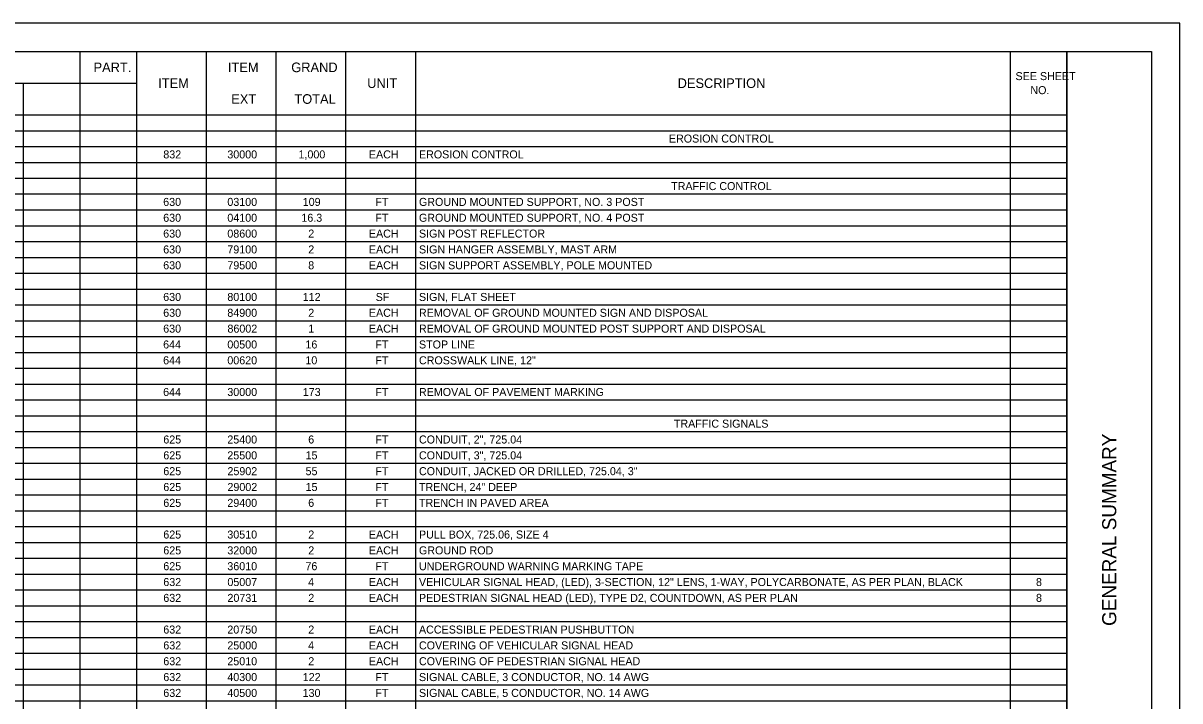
# Model space of a CAD drawing. Extents: x 0 to 34, y 0 to 22.
# Drawn here: x 13.53 to 34, y 10.02 to 22 of the extents above; entities that cross this region are included whole.
import ezdxf

# ---------------------------------------------------------------- set-up
doc = ezdxf.new("R2010")
doc.units = 0
for name, color, linetype in [('Default', 7, 'Continuous'), ('SH_Border', 7, 'Continuous'), ('SH_Cut_Line', 7, 'Continuous'), ('SH_Data', 7, 'Continuous')]:
    doc.layers.add(name, color=color, linetype=linetype)

msp = doc.modelspace()

# ---------------------------------------------------------------- linework, layer by layer
at = {"layer": 'Default'}
for p, q in [((12.528, 21.499), (13.53, 21.499)), ((13.53, 21.499), (15.535, 21.499)), ((14.533, 21.499), (14.533, 21.219)), ((15.535, 21.499), (32, 21.499)), ((15.535, 21.499), (15.535, 21.219)), ((16.769, 21.499), (16.769, 21.219)), ((18.003, 21.499), (18.003, 21.219)), ((19.237, 21.499), (19.237, 21.219)), ((20.471, 21.499), (20.471, 21.219)), ((30.997, 21.499), (30.997, 21.219)), ((32, 21.499), (32, 21.219)), ((14.533, 21.219), (14.533, 20.939)), ((15.535, 21.219), (15.535, 20.939)), ((16.769, 21.219), (16.769, 20.939)), ((18.003, 21.219), (18.003, 20.939)), ((19.237, 21.219), (19.237, 20.939)), ((20.471, 21.219), (20.471, 20.939)), ((30.997, 21.219), (30.997, 20.939)), ((32, 21.219), (32, 20.939)), ((12.528, 20.939), (13.53, 20.939)), ((13.53, 20.939), (15.535, 20.939)), ((13.53, 20.939), (13.53, 20.659)), ((14.533, 20.939), (14.533, 20.659)), ((15.535, 20.939), (15.535, 20.659)), ((16.769, 20.939), (16.769, 20.659)), ((18.003, 20.939), (18.003, 20.659)), ((19.237, 20.939), (19.237, 20.659)), ((20.471, 20.939), (20.471, 20.659)), ((30.997, 20.939), (30.997, 20.659)), ((32, 20.939), (32, 20.659)), ((13.53, 20.659), (13.53, 20.379)), ((14.533, 20.659), (14.533, 20.379)), ((15.535, 20.659), (15.535, 20.379)), ((16.769, 20.659), (16.769, 20.379)), ((18.003, 20.659), (18.003, 20.379)), ((19.237, 20.659), (19.237, 20.379)), ((20.471, 20.659), (20.471, 20.379)), ((30.997, 20.659), (30.997, 20.379)), ((32, 20.659), (32, 20.379)), ((12.528, 20.379), (13.53, 20.379)), ((13.53, 20.379), (15.535, 20.379)), ((13.53, 20.379), (13.53, 20.099)), ((14.533, 20.379), (14.533, 20.099)), ((15.535, 20.379), (32, 20.379)), ((15.535, 20.379), (15.535, 20.099)), ((16.769, 20.379), (16.769, 20.099)), ((18.003, 20.379), (18.003, 20.099)), ((19.237, 20.379), (19.237, 20.099)), ((20.471, 20.379), (20.471, 20.099)), ((30.997, 20.379), (30.997, 20.099)), ((32, 20.379), (32, 20.099)), ((12.528, 20.099), (13.53, 20.099)), ((13.53, 20.099), (15.535, 20.099)), ((13.53, 20.099), (13.53, 18.7)), ((14.533, 20.099), (14.533, 18.7)), ((15.535, 20.099), (32, 20.099)), ((15.535, 20.099), (15.535, 18.7)), ((16.769, 20.099), (16.769, 18.7)), ((18.003, 20.099), (18.003, 18.7)), ((19.237, 20.099), (19.237, 18.7)), ((20.471, 20.099), (20.471, 18.7)), ((30.997, 20.099), (30.997, 18.7)), ((32, 20.099), (32, 18.7)), ((12.528, 19.819), (13.53, 19.819)), ((13.53, 19.819), (15.535, 19.819)), ((15.535, 19.819), (32, 19.819)), ((12.528, 19.539), (13.53, 19.539)), ((13.53, 19.539), (15.535, 19.539)), ((15.535, 19.539), (32, 19.539)), ((12.528, 19.259), (13.53, 19.259)), ((13.53, 19.259), (15.535, 19.259)), ((15.535, 19.259), (32, 19.259)), ((12.528, 18.98), (13.53, 18.98)), ((13.53, 18.98), (15.535, 18.98)), ((15.535, 18.98), (32, 18.98)), ((12.528, 18.7), (13.53, 18.7)), ((13.53, 18.7), (15.535, 18.7)), ((13.53, 18.7), (13.53, 18.14)), ((14.533, 18.7), (14.533, 18.14)), ((15.535, 18.7), (32, 18.7)), ((15.535, 18.7), (15.535, 18.14)), ((16.769, 18.7), (16.769, 18.14)), ((18.003, 18.7), (18.003, 18.14)), ((19.237, 18.7), (19.237, 18.14)), ((20.471, 18.7), (20.471, 18.14)), ((30.997, 18.7), (30.997, 18.14)), ((32, 18.7), (32, 18.14)), ((12.528, 18.42), (13.53, 18.42)), ((13.53, 18.42), (15.535, 18.42)), ((15.535, 18.42), (32, 18.42)), ((12.528, 18.14), (13.53, 18.14)), ((13.53, 18.14), (15.535, 18.14)), ((13.53, 18.14), (13.53, 17.86)), ((14.533, 18.14), (14.533, 17.86)), ((15.535, 18.14), (32, 18.14)), ((15.535, 18.14), (15.535, 17.86)), ((16.769, 18.14), (16.769, 17.86)), ((18.003, 18.14), (18.003, 17.86)), ((19.237, 18.14), (19.237, 17.86)), ((20.471, 18.14), (20.471, 17.86)), ((30.997, 18.14), (30.997, 17.86)), ((32, 18.14), (32, 17.86)), ((12.528, 17.86), (13.53, 17.86)), ((13.53, 17.86), (15.535, 17.86)), ((13.53, 17.86), (13.53, 17.58)), ((14.533, 17.86), (14.533, 17.58)), ((15.535, 17.86), (32, 17.86)), ((15.535, 17.86), (15.535, 17.58)), ((16.769, 17.86), (16.769, 17.58)), ((18.003, 17.86), (18.003, 17.58)), ((19.237, 17.86), (19.237, 17.58)), ((20.471, 17.86), (20.471, 17.58)), ((30.997, 17.86), (30.997, 17.58)), ((32, 17.86), (32, 17.58)), ((12.528, 17.58), (13.53, 17.58)), ((13.53, 17.58), (15.535, 17.58)), ((13.53, 17.58), (13.53, 17.3)), ((14.533, 17.58), (14.533, 17.3)), ((15.535, 17.58), (32, 17.58)), ((15.535, 17.58), (15.535, 17.3)), ((16.769, 17.58), (16.769, 17.3)), ((18.003, 17.58), (18.003, 17.3)), ((19.237, 17.58), (19.237, 17.3)), ((20.471, 17.58), (20.471, 17.3)), ((30.997, 17.58), (30.997, 17.3)), ((32, 17.58), (32, 17.3)), ((12.528, 17.3), (13.53, 17.3)), ((13.53, 17.3), (15.535, 17.3)), ((13.53, 17.3), (13.53, 17.02)), ((14.533, 17.3), (14.533, 17.02)), ((15.535, 17.3), (32, 17.3)), ((15.535, 17.3), (15.535, 17.02)), ((16.769, 17.3), (16.769, 17.02)), ((18.003, 17.3), (18.003, 17.02)), ((19.237, 17.3), (19.237, 17.02)), ((20.471, 17.3), (20.471, 17.02)), ((30.997, 17.3), (30.997, 17.02)), ((32, 17.3), (32, 17.02)), ((12.528, 17.02), (13.53, 17.02)), ((13.53, 17.02), (15.535, 17.02)), ((13.53, 17.02), (13.53, 16.74)), ((14.533, 17.02), (14.533, 16.74)), ((15.535, 17.02), (32, 17.02)), ((15.535, 17.02), (15.535, 16.74)), ((16.769, 17.02), (16.769, 16.74)), ((18.003, 17.02), (18.003, 16.74)), ((19.237, 17.02), (19.237, 16.74)), ((20.471, 17.02), (20.471, 16.74)), ((30.997, 17.02), (30.997, 16.74)), ((32, 17.02), (32, 16.74)), ((12.528, 16.74), (13.53, 16.74)), ((13.53, 16.74), (15.535, 16.74)), ((13.53, 16.74), (13.53, 16.18)), ((14.533, 16.74), (14.533, 16.18)), ((15.535, 16.74), (32, 16.74)), ((15.535, 16.74), (15.535, 16.18)), ((16.769, 16.74), (16.769, 16.18)), ((18.003, 16.74), (18.003, 16.18)), ((19.237, 16.74), (19.237, 16.18)), ((20.471, 16.74), (20.471, 16.18)), ((30.997, 16.74), (30.997, 16.18)), ((32, 16.74), (32, 16.18)), ((12.528, 16.46), (13.53, 16.46)), ((13.53, 16.46), (15.535, 16.46)), ((15.535, 16.46), (32, 16.46)), ((12.528, 16.18), (13.53, 16.18)), ((13.53, 16.18), (15.535, 16.18)), ((13.53, 16.18), (13.53, 15.9)), ((14.533, 16.18), (14.533, 15.9)), ((15.535, 16.18), (32, 16.18)), ((15.535, 16.18), (15.535, 15.9)), ((16.769, 16.18), (16.769, 15.9)), ((18.003, 16.18), (18.003, 15.9)), ((19.237, 16.18), (19.237, 15.9)), ((20.471, 16.18), (20.471, 15.9)), ((30.997, 16.18), (30.997, 15.9)), ((32, 16.18), (32, 15.9)), ((12.528, 15.9), (13.53, 15.9)), ((13.53, 15.9), (15.535, 15.9)), ((13.53, 15.9), (13.53, 15.62)), ((14.533, 15.9), (14.533, 15.62)), ((15.535, 15.9), (32, 15.9)), ((15.535, 15.9), (15.535, 15.62)), ((16.769, 15.9), (16.769, 15.62)), ((18.003, 15.9), (18.003, 15.62)), ((19.237, 15.9), (19.237, 15.62)), ((20.471, 15.9), (20.471, 15.62)), ((30.997, 15.9), (30.997, 15.62)), ((32, 15.9), (32, 15.62)), ((12.528, 15.62), (13.53, 15.62)), ((13.53, 15.62), (15.535, 15.62)), ((13.53, 15.62), (13.53, 15.34)), ((14.533, 15.62), (14.533, 15.34)), ((15.535, 15.62), (32, 15.62)), ((15.535, 15.62), (15.535, 15.34)), ((16.769, 15.62), (16.769, 15.34)), ((18.003, 15.62), (18.003, 15.34)), ((19.237, 15.62), (19.237, 15.34)), ((20.471, 15.62), (20.471, 15.34)), ((30.997, 15.62), (30.997, 15.34)), ((32, 15.62), (32, 15.34)), ((12.528, 15.34), (13.53, 15.34)), ((13.53, 15.34), (15.535, 15.34)), ((13.53, 15.34), (13.53, 14.78)), ((14.533, 15.34), (14.533, 14.78)), ((15.535, 15.34), (32, 15.34)), ((15.535, 15.34), (15.535, 14.78)), ((16.769, 15.34), (16.769, 14.78)), ((18.003, 15.34), (18.003, 14.78)), ((19.237, 15.34), (19.237, 14.78)), ((20.471, 15.34), (20.471, 14.78)), ((30.997, 15.34), (30.997, 14.78)), ((32, 15.34), (32, 14.78)), ((12.528, 15.06), (13.53, 15.06)), ((13.53, 15.06), (15.535, 15.06)), ((15.535, 15.06), (32, 15.06)), ((12.528, 14.78), (13.53, 14.78)), ((13.53, 14.78), (15.535, 14.78)), ((13.53, 14.78), (13.53, 14.5)), ((14.533, 14.78), (14.533, 14.5)), ((15.535, 14.78), (32, 14.78)), ((15.535, 14.78), (15.535, 14.5)), ((16.769, 14.78), (16.769, 14.5)), ((18.003, 14.78), (18.003, 14.5)), ((19.237, 14.78), (19.237, 14.5)), ((20.471, 14.78), (20.471, 14.5)), ((30.997, 14.78), (30.997, 14.5)), ((32, 14.78), (32, 14.5)), ((12.528, 14.5), (13.53, 14.5)), ((13.53, 14.5), (15.535, 14.5)), ((13.53, 14.5), (13.53, 14.22)), ((14.533, 14.5), (14.533, 14.22)), ((15.535, 14.5), (32, 14.5)), ((15.535, 14.5), (15.535, 14.22)), ((16.769, 14.5), (16.769, 14.22)), ((18.003, 14.5), (18.003, 14.22)), ((19.237, 14.5), (19.237, 14.22)), ((20.471, 14.5), (20.471, 14.22)), ((30.997, 14.5), (30.997, 14.22)), ((32, 14.5), (32, 14.22)), ((12.528, 14.22), (13.53, 14.22)), ((13.53, 14.22), (15.535, 14.22)), ((13.53, 14.22), (13.53, 13.94)), ((14.533, 14.22), (14.533, 13.94)), ((15.535, 14.22), (32, 14.22)), ((15.535, 14.22), (15.535, 13.94)), ((16.769, 14.22), (16.769, 13.94)), ((18.003, 14.22), (18.003, 13.94)), ((19.237, 14.22), (19.237, 13.94)), ((20.471, 14.22), (20.471, 13.94)), ((30.997, 14.22), (30.997, 13.94)), ((32, 14.22), (32, 13.94)), ((12.528, 13.94), (13.53, 13.94)), ((13.53, 13.94), (15.535, 13.94)), ((13.53, 13.94), (13.53, 11.7)), ((14.533, 13.94), (14.533, 11.7)), ((15.535, 13.94), (32, 13.94)), ((15.535, 13.94), (15.535, 11.7)), ((16.769, 13.94), (16.769, 11.7)), ((18.003, 13.94), (18.003, 11.7)), ((19.237, 13.94), (19.237, 11.7)), ((20.471, 13.94), (20.471, 11.7)), ((30.997, 13.94), (30.997, 11.7)), ((32, 13.94), (32, 11.7)), ((12.528, 13.66), (13.53, 13.66)), ((13.53, 13.66), (15.535, 13.66)), ((15.535, 13.66), (32, 13.66)), ((12.528, 13.38), (13.53, 13.38)), ((13.53, 13.38), (15.535, 13.38)), ((15.535, 13.38), (32, 13.38)), ((12.528, 13.1), (13.53, 13.1)), ((13.53, 13.1), (15.535, 13.1)), ((15.535, 13.1), (32, 13.1)), ((12.528, 12.82), (13.53, 12.82)), ((13.53, 12.82), (15.535, 12.82)), ((15.535, 12.82), (32, 12.82)), ((12.528, 12.54), (13.53, 12.54)), ((13.53, 12.54), (15.535, 12.54)), ((15.535, 12.54), (32, 12.54)), ((12.528, 12.26), (13.53, 12.26)), ((13.53, 12.26), (15.535, 12.26)), ((15.535, 12.26), (32, 12.26)), ((12.528, 11.98), (13.53, 11.98)), ((13.53, 11.98), (15.535, 11.98)), ((15.535, 11.98), (32, 11.98)), ((12.528, 11.7), (13.53, 11.7)), ((13.53, 11.7), (15.535, 11.7)), ((13.53, 11.7), (13.53, 11.42)), ((14.533, 11.7), (14.533, 11.42)), ((15.535, 11.7), (32, 11.7)), ((15.535, 11.7), (15.535, 11.42)), ((16.769, 11.7), (16.769, 11.42)), ((18.003, 11.7), (18.003, 11.42)), ((19.237, 11.7), (19.237, 11.42)), ((20.471, 11.7), (20.471, 11.42)), ((30.997, 11.7), (30.997, 11.42)), ((32, 11.7), (32, 11.42)), ((12.528, 11.42), (13.53, 11.42)), ((13.53, 11.42), (15.535, 11.42)), ((13.53, 11.42), (13.53, 10.3)), ((14.533, 11.42), (14.533, 10.3)), ((15.535, 11.42), (32, 11.42)), ((15.535, 11.42), (15.535, 10.3)), ((16.769, 11.42), (16.769, 10.3)), ((18.003, 11.42), (18.003, 10.3)), ((19.237, 11.42), (19.237, 10.3)), ((20.471, 11.42), (20.471, 10.3)), ((30.997, 11.42), (30.997, 10.3)), ((32, 11.42), (32, 10.3)), ((12.528, 11.14), (13.53, 11.14)), ((13.53, 11.14), (15.535, 11.14)), ((15.535, 11.14), (32, 11.14)), ((12.528, 10.86), (13.53, 10.86)), ((13.53, 10.86), (15.535, 10.86)), ((15.535, 10.86), (32, 10.86)), ((12.528, 10.58), (13.53, 10.58)), ((13.53, 10.58), (15.535, 10.58)), ((15.535, 10.58), (32, 10.58)), ((12.528, 10.3), (13.53, 10.3)), ((13.53, 10.3), (15.535, 10.3)), ((13.53, 10.3), (13.53, 10.02)), ((14.533, 10.3), (14.533, 10.02)), ((15.535, 10.3), (32, 10.3)), ((15.535, 10.3), (15.535, 10.02)), ((16.769, 10.3), (16.769, 10.02)), ((18.003, 10.3), (18.003, 10.02)), ((19.237, 10.3), (19.237, 10.02)), ((20.471, 10.3), (20.471, 10.02)), ((30.997, 10.3), (30.997, 10.02)), ((32, 10.3), (32, 10.02)), ((12.528, 10.02), (13.53, 10.02)), ((13.53, 10.02), (15.535, 10.02)), ((13.53, 10.02), (13.53, 9.74)), ((14.533, 10.02), (14.533, 9.74)), ((15.535, 10.02), (32, 10.02)), ((15.535, 10.02), (15.535, 9.74)), ((16.769, 10.02), (16.769, 9.74)), ((18.003, 10.02), (18.003, 9.74)), ((19.237, 10.02), (19.237, 9.74)), ((20.471, 10.02), (20.471, 9.74)), ((30.997, 10.02), (30.997, 9.74)), ((32, 10.02), (32, 9.74))]:
    msp.add_line(p, q, dxfattribs=at)
at = {"layer": 'SH_Border'}
msp.add_line((32, 0.5), (32, 21.5), dxfattribs=at)
msp.add_lwpolyline([(1.5, 21.5), (33.5, 21.5), (33.5, 0.5), (1.5, 0.5)], close=True, dxfattribs=at)
at = {"layer": 'SH_Cut_Line'}
msp.add_lwpolyline([(0, 0), (34, 0), (34, 22), (0, 22)], close=True, dxfattribs=at)

# ---------------------------------------------------------------- texts
at = {"layer": 'Default'}
for s, height, p in [('PART.', 0.17, (14.776, 21.134)), ('ITEM', 0.17, (17.154, 21.134)), ('GRAND', 0.17, (18.275, 21.134)), ('SEE SHEET ', 0.1417, (31.092, 20.993)), ('ITEM', 0.17, (15.92, 20.854)), ('UNIT', 0.17, (19.619, 20.854)), ('DESCRIPTION', 0.17, (25.112, 20.854)), ('NO.', 0.1417, (31.355, 20.745)), ('EXT', 0.17, (17.213, 20.574)), ('TOTAL', 0.17, (18.33, 20.574)), ('EROSION CONTROL', 0.14166, (24.958, 19.889)), ('832', 0.1417, (16.011, 19.609)), ('30000', 0.1417, (17.144, 19.609)), ('1,000', 0.1417, (18.403, 19.609)), ('EACH', 0.1417, (19.649, 19.609)), ('EROSION CONTROL', 0.14166, (20.535, 19.609)), ('TRAFFIC CONTROL', 0.14166, (24.998, 19.049)), ('630', 0.1417, (16.009, 18.769)), ('03100', 0.1417, (17.144, 18.769)), ('109', 0.1417, (18.478, 18.769)), ('FT', 0.1417, (19.763, 18.769)), ('GROUND MOUNTED SUPPORT, NO. 3 POST', 0.14166, (20.535, 18.769)), ('630', 0.1417, (16.009, 18.489)), ('04100', 0.1417, (17.144, 18.489)), ('16.3', 0.1417, (18.454, 18.489)), ('FT', 0.1417, (19.763, 18.489)), ('GROUND MOUNTED SUPPORT, NO. 4 POST', 0.14166, (20.535, 18.489)), ('630', 0.1417, (16.009, 18.209)), ('08600', 0.1417, (17.144, 18.209)), ('2', 0.142, (18.576, 18.209)), ('EACH', 0.1417, (19.649, 18.209)), ('SIGN POST REFLECTOR', 0.14166, (20.535, 18.209)), ('630', 0.1417, (16.009, 17.929)), ('79100', 0.1417, (17.144, 17.929)), ('2', 0.142, (18.576, 17.929)), ('EACH', 0.1417, (19.649, 17.929)), ('SIGN HANGER ASSEMBLY, MAST ARM', 0.14166, (20.535, 17.929)), ('630', 0.1417, (16.009, 17.649)), ('79500', 0.1417, (17.144, 17.649)), ('8', 0.142, (18.575, 17.649)), ('EACH', 0.1417, (19.649, 17.649)), ('SIGN SUPPORT ASSEMBLY, POLE MOUNTED', 0.14166, (20.535, 17.649)), ('630', 0.1417, (16.009, 17.089)), ('80100', 0.1417, (17.144, 17.089)), ('112', 0.1417, (18.478, 17.089)), ('SF', 0.1417, (19.769, 17.089)), ('SIGN, FLAT SHEET', 0.14166, (20.535, 17.089)), ('630', 0.1417, (16.009, 16.809)), ('84900', 0.1417, (17.144, 16.809)), ('2', 0.142, (18.576, 16.809)), ('EACH', 0.1417, (19.649, 16.809)), ('REMOVAL OF GROUND MOUNTED SIGN AND DISPOSAL', 0.14166, (20.535, 16.809)), ('630', 0.1417, (16.009, 16.529)), ('86002', 0.1417, (17.146, 16.529)), ('1', 0.142, (18.576, 16.529)), ('EACH', 0.1417, (19.649, 16.529)), ('REMOVAL OF GROUND MOUNTED POST SUPPORT AND DISPOSAL', 0.14166, (20.535, 16.529)), ('644', 0.1417, (16.008, 16.249)), ('00500', 0.1417, (17.144, 16.249)), ('16', 0.1417, (18.526, 16.249)), ('FT', 0.1417, (19.763, 16.249)), ('STOP LINE', 0.1417, (20.535, 16.249)), ('644', 0.1417, (16.008, 15.969)), ('00620', 0.1417, (17.144, 15.969)), ('10', 0.1417, (18.525, 15.969)), ('FT', 0.1417, (19.763, 15.969)), ('CROSSWALK LINE, 12"', 0.14166, (20.535, 15.969)), ('644', 0.1417, (16.008, 15.409)), ('30000', 0.1417, (17.144, 15.409)), ('173', 0.1417, (18.479, 15.409)), ('FT', 0.1417, (19.763, 15.409)), ('REMOVAL OF PAVEMENT MARKING', 0.14166, (20.535, 15.409)), ('TRAFFIC SIGNALS', 0.14166, (25.046, 14.849)), ('625', 0.1417, (16.011, 14.569)), ('25400', 0.1417, (17.144, 14.569)), ('6', 0.142, (18.575, 14.569)), ('FT', 0.1417, (19.763, 14.569)), ('CONDUIT, 2", 725.04', 0.14166, (20.535, 14.569)), ('625', 0.1417, (16.011, 14.289)), ('25500', 0.1417, (17.144, 14.289)), ('15', 0.1417, (18.528, 14.289)), ('FT', 0.1417, (19.763, 14.289)), ('CONDUIT, 3", 725.04', 0.14166, (20.535, 14.289)), ('625', 0.1417, (16.011, 14.009)), ('25902', 0.1417, (17.146, 14.009)), ('55', 0.1417, (18.528, 14.009)), ('FT', 0.1417, (19.763, 14.009)), ('CONDUIT, JACKED OR DRILLED, 725.04, 3"', 0.14166, (20.535, 14.009)), ('625', 0.1417, (16.011, 13.729)), ('29002', 0.1417, (17.146, 13.729)), ('15', 0.1417, (18.528, 13.729)), ('FT', 0.1417, (19.763, 13.729)), ('TRENCH, 24" DEEP', 0.14166, (20.535, 13.729)), ('625', 0.1417, (16.011, 13.449)), ('29400', 0.1417, (17.144, 13.449)), ('6', 0.142, (18.575, 13.449)), ('FT', 0.1417, (19.763, 13.449)), ('TRENCH IN PAVED AREA', 0.14166, (20.535, 13.449)), ('625', 0.1417, (16.011, 12.889)), ('30510', 0.1417, (17.144, 12.889)), ('2', 0.142, (18.576, 12.889)), ('EACH', 0.1417, (19.649, 12.889)), ('PULL BOX, 725.06, SIZE 4', 0.14166, (20.535, 12.889)), ('625', 0.1417, (16.011, 12.609)), ('32000', 0.1417, (17.144, 12.609)), ('2', 0.142, (18.576, 12.609)), ('EACH', 0.1417, (19.649, 12.609)), ('GROUND ROD', 0.1417, (20.535, 12.609)), ('625', 0.1417, (16.011, 12.329)), ('36010', 0.1417, (17.144, 12.329)), ('76', 0.1417, (18.526, 12.329)), ('FT', 0.1417, (19.763, 12.329)), ('UNDERGROUND WARNING MARKING TAPE', 0.14166, (20.535, 12.329)), ('632', 0.1417, (16.011, 12.049)), ('05007', 0.1417, (17.145, 12.049)), ('4', 0.142, (18.574, 12.049)), ('EACH', 0.1417, (19.649, 12.049)), ('VEHICULAR SIGNAL HEAD, (LED), 3-SECTION, 12" LENS, 1-WAY, POLYCARBONATE, AS PER PLAN, BLACK', 0.14166, (20.535, 12.049)), ('8', 0.142, (31.454, 12.049)), ('632', 0.1417, (16.011, 11.769)), ('20731', 0.1417, (17.146, 11.769)), ('2', 0.142, (18.576, 11.769)), ('EACH', 0.1417, (19.649, 11.769)), ('PEDESTRIAN SIGNAL HEAD (LED), TYPE D2, COUNTDOWN, AS PER PLAN', 0.14166, (20.535, 11.769)), ('8', 0.142, (31.454, 11.769)), ('632', 0.1417, (16.011, 11.209)), ('20750', 0.1417, (17.144, 11.209)), ('2', 0.142, (18.576, 11.209)), ('EACH', 0.1417, (19.649, 11.209)), ('ACCESSIBLE PEDESTRIAN PUSHBUTTON', 0.14166, (20.535, 11.209)), ('632', 0.1417, (16.011, 10.929)), ('25000', 0.1417, (17.144, 10.929)), ('4', 0.142, (18.574, 10.929)), ('EACH', 0.1417, (19.649, 10.929)), ('COVERING OF VEHICULAR SIGNAL HEAD', 0.14166, (20.535, 10.929)), ('632', 0.1417, (16.011, 10.649)), ('25010', 0.1417, (17.144, 10.649)), ('2', 0.142, (18.576, 10.649)), ('EACH', 0.1417, (19.649, 10.649)), ('COVERING OF PEDESTRIAN SIGNAL HEAD', 0.14166, (20.535, 10.649)), ('632', 0.1417, (16.011, 10.369)), ('40300', 0.1417, (17.144, 10.369)), ('122', 0.1417, (18.478, 10.369)), ('FT', 0.1417, (19.763, 10.369)), ('SIGNAL CABLE, 3 CONDUCTOR, NO. 14 AWG', 0.14166, (20.535, 10.369)), ('632', 0.1417, (16.011, 10.089)), ('40500', 0.1417, (17.144, 10.089)), ('130', 0.1417, (18.476, 10.089)), ('FT', 0.1417, (19.763, 10.089)), ('SIGNAL CABLE, 5 CONDUCTOR, NO. 14 AWG', 0.14166, (20.535, 10.089))]:
    msp.add_text(s, height=height, dxfattribs=at).set_placement(p)
at = {"layer": 'SH_Data'}
msp.add_text('GENERAL SUMMARY', height=0.25, rotation=90, dxfattribs=at).set_placement((32.875, 11.344))

doc.saveas('drawing.dxf')
